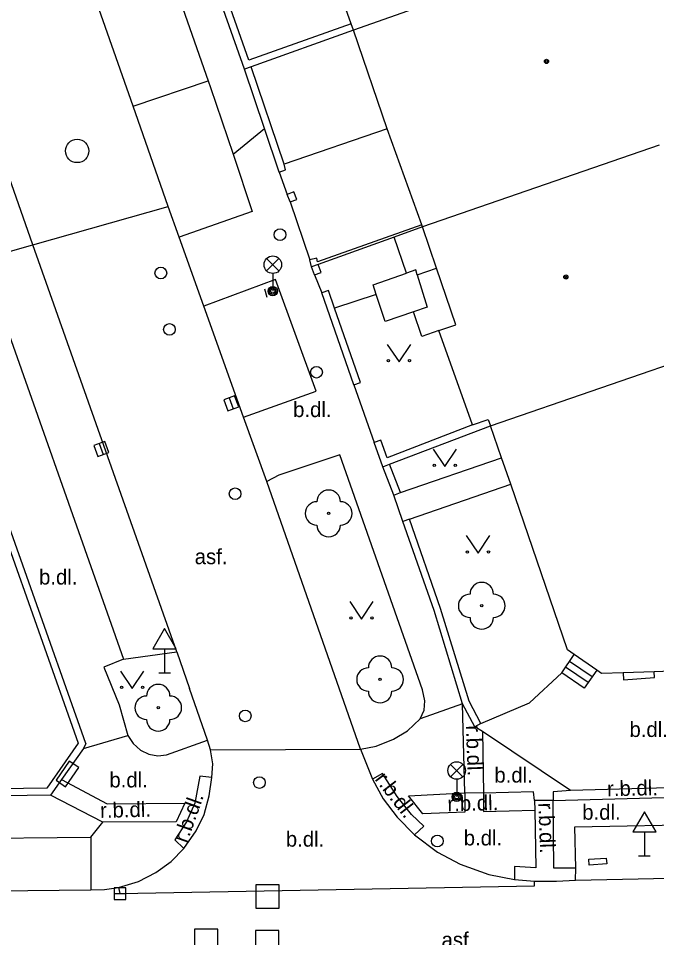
# Model space of a CAD drawing. Extents: x -596229 to -595156, y -1161237 to -1159376.
# Drawn here: x -595847.54 to -595820.24, y -1160892.51 to -1160853.2 of the extents above; entities that cross this region are included whole.
import ezdxf

# ---------------------------------------------------------------- set-up
doc = ezdxf.new("R2010")
doc.units = 0
for name, color, linetype in [('Level 22', 7, 'Continuous'), ('Level 24', 7, 'Continuous'), ('Level 26', 7, 'Continuous'), ('Level 27', 7, 'Continuous'), ('Level 28', 7, 'Continuous'), ('Level 31', 7, 'Continuous'), ('Level 33', 7, 'Continuous'), ('Level 34', 7, 'Continuous'), ('Level 36', 7, 'Continuous'), ('Level 39', 7, 'Continuous'), ('slaboproud - povrch.  znaky a tel. budka skut. velikost', 7, 'Continuous'), ('Specificka linie pasportu komunikaci', 7, 'Continuous'), ('TM - budovy zdene_ betonove - VP', 7, 'Continuous'), ('TM - chodniky - VP', 7, 'Continuous'), ('TM - komunikace - VP', 7, 'Continuous'), ('TM - letecke snimky - pomocna linie', 7, 'Continuous'), ('TM - plot drateny_ kovovy - VP', 7, 'Continuous'), ('TM - podezdivka plotu - VP', 7, 'Continuous'), ('TM - popis povrchu', 7, 'Continuous'), ('TM - rozhrani mezi zpev. plochami mezi sebou - VP', 7, 'Continuous'), ('TM - rozhrani ploch obecne - VP', 7, 'Continuous'), ('TM - schody - VP', 7, 'Continuous'), ('TM - vjezd na pozemek', 7, 'Continuous'), ('TM - zabradli - VP', 7, 'Continuous')]:
    doc.layers.add(name, color=color, linetype=linetype)

msp = doc.modelspace()

# ---------------------------------------------------------------- linework, layer by layer
at = {"layer": 'Level 22'}
for centre in [(-595834.27, -1160874.37), (-595827.72, -1160878.32), (-595832.07, -1160881.47), (-595841.56, -1160882.68)]:
    msp.add_circle(centre, 0.05, dxfattribs=at)
for centre, start, end in [((-595834.27, -1160873.87), 0, 180), ((-595834.77, -1160874.37), 90, 270), ((-595833.77, -1160874.37), 270, 90), ((-595834.27, -1160874.87), 180, 0), ((-595827.72, -1160877.82), 0, 180), ((-595828.22, -1160878.32), 90, 270), ((-595827.22, -1160878.32), 270, 90), ((-595827.72, -1160878.82), 180, 0), ((-595832.07, -1160880.97), 0, 180), ((-595832.57, -1160881.47), 90, 270), ((-595831.57, -1160881.47), 270, 90), ((-595841.56, -1160882.18), 0, 180), ((-595832.07, -1160881.97), 180, 0), ((-595842.06, -1160882.68), 90, 270), ((-595841.06, -1160882.68), 270, 90), ((-595841.56, -1160883.18), 180, 0)]:
    msp.add_arc(centre, 0.5, start, end, dxfattribs=at)
at = {"layer": 'Level 24'}
msp.add_lwpolyline([(-595845.369, -1160884.958), (-595845.934, -1160885.783), (-595845.522, -1160886.066), (-595844.957, -1160885.24)], close=True, dxfattribs=at)
at = {"layer": 'Level 26'}
for points in [[(-595837.39, -1160891.25), (-595836.39, -1160891.25), (-595836.39, -1160890.25), (-595837.39, -1160890.25)], [(-595840.01, -1160893.15), (-595839.01, -1160893.15), (-595839.01, -1160892.15), (-595840.01, -1160892.15)], [(-595837.4, -1160893.21), (-595836.4, -1160893.21), (-595836.4, -1160892.21), (-595837.4, -1160892.21)]]:
    msp.add_lwpolyline(points, close=True, dxfattribs=at)
at = {"layer": 'Level 27'}
for p, q in [((-595838.527, -1160869.425), (-595838.353, -1160869.894)), ((-595844.087, -1160871.386), (-595843.913, -1160871.854)), ((-595843.45, -1160890.63), (-595842.95, -1160890.63))]:
    msp.add_line(p, q, dxfattribs=at)
for points in [[(-595838.761, -1160869.512), (-595838.588, -1160869.981), (-595838.119, -1160869.808), (-595838.292, -1160869.339)], [(-595844.321, -1160871.472), (-595844.148, -1160871.941), (-595843.679, -1160871.768), (-595843.852, -1160871.299)], [(-595843.45, -1160890.88), (-595842.95, -1160890.88), (-595842.95, -1160890.38), (-595843.45, -1160890.38)]]:
    msp.add_lwpolyline(points, close=True, dxfattribs=at)
msp.add_circle((-595845.03, -1160858.87), 0.5, dxfattribs=at)
at = {"layer": 'Level 28'}
for centre in [(-595836.35, -1160862.45), (-595841.45, -1160864.09), (-595841.08, -1160866.5), (-595834.79, -1160868.33), (-595838.27, -1160873.53)]:
    msp.add_circle(centre, 0.25, dxfattribs=at)
at = {"layer": 'Level 31'}
for centre in [(-595837.84, -1160883.03), (-595837.23, -1160885.88), (-595829.62, -1160888.38)]:
    msp.add_circle(centre, 0.25, dxfattribs=at)
at = {"layer": 'Level 33'}
for p, q in [((-595836.925, -1160864), (-595836.395, -1160863.47)), ((-595836.925, -1160863.47), (-595836.395, -1160864)), ((-595836.66, -1160864.11), (-595836.66, -1160864.86)), ((-595829.055, -1160885.63), (-595828.525, -1160885.1)), ((-595829.055, -1160885.1), (-595828.525, -1160885.63)), ((-595828.79, -1160885.74), (-595828.79, -1160886.49))]:
    msp.add_line(p, q, dxfattribs=at)
for centre, radius in [((-595836.66, -1160863.735), 0.375), ((-595836.66, -1160864.86), 0.2), ((-595836.66, -1160864.86), 0.145), ((-595836.66, -1160864.86), 0.0876), ((-595828.79, -1160885.365), 0.375), ((-595828.79, -1160886.49), 0.2), ((-595828.79, -1160886.49), 0.145), ((-595828.79, -1160886.49), 0.0876)]:
    msp.add_circle(centre, radius, dxfattribs=at)
at = {"layer": 'Level 34'}
for p, q in [((-595841.29, -1160880.162), (-595841.29, -1160881.18)), ((-595841.54, -1160881.18), (-595841.04, -1160881.18)), ((-595820.76, -1160887.992), (-595820.76, -1160889.01)), ((-595821.01, -1160889.01), (-595820.51, -1160889.01))]:
    msp.add_line(p, q, dxfattribs=at)
for points in [[(-595841.79, -1160880.162), (-595840.79, -1160880.162), (-595841.29, -1160879.296)], [(-595821.26, -1160887.992), (-595820.26, -1160887.992), (-595820.76, -1160887.126)]]:
    msp.add_lwpolyline(points, close=True, dxfattribs=at)
at = {"layer": 'Level 36'}
for points in [[(-595831.76, -1160867.14), (-595831.26, -1160867.89), (-595830.76, -1160867.14)], [(-595829.8, -1160871.62), (-595829.3, -1160872.37), (-595828.8, -1160871.62)], [(-595828.38, -1160875.32), (-595827.88, -1160876.07), (-595827.38, -1160875.32)], [(-595833.37, -1160878.14), (-595832.87, -1160878.89), (-595832.37, -1160878.14)], [(-595843.18, -1160881.11), (-595842.68, -1160881.86), (-595842.18, -1160881.11)]]:
    msp.add_lwpolyline(points, dxfattribs=at)
for centre in [(-595831.71, -1160867.84), (-595830.811, -1160867.84), (-595829.75, -1160872.32), (-595828.851, -1160872.32), (-595828.33, -1160876.02), (-595827.431, -1160876.02), (-595833.32, -1160878.84), (-595832.421, -1160878.84), (-595843.13, -1160881.81), (-595842.231, -1160881.81)]:
    msp.add_circle(centre, 0.05, dxfattribs=at)
at = {"layer": 'Level 39'}
for centre, radius in [((-595824.95, -1160855.04), 0.09), ((-595824.95, -1160855.04), 0.0398), ((-595824.12, -1160864.26), 0.09), ((-595824.12, -1160864.26), 0.0398)]:
    msp.add_circle(centre, radius, dxfattribs=at)
at = {"layer": 'slaboproud - povrch.  znaky a tel. budka skut. velikost'}
msp.add_lwpolyline([(-595823.14, -1160889.16), (-595822.39, -1160889.11), (-595822.37, -1160889.36), (-595823.12, -1160889.41), (-595823.14, -1160889.16)], dxfattribs=at)
at = {"layer": 'Specificka linie pasportu komunikaci'}
for points in [[(-595845.03, -1160843.46), (-595843.86, -1160843.2), (-595839.42, -1160855.87)], [(-595842.64, -1160856.96), (-595844.83, -1160850.7), (-595847.01, -1160844.7)], [(-595842.64, -1160856.96), (-595839.42, -1160855.87)], [(-595839.42, -1160855.87), (-595839.32, -1160856.15), (-595838.36, -1160859)], [(-595841.13, -1160861.25), (-595842.64, -1160856.96)], [(-595838.36, -1160859), (-595837.01, -1160857.91)], [(-595838.36, -1160859), (-595837.54, -1160861.46), (-595840.67, -1160862.55)], [(-595846.92, -1160862.88), (-595841.13, -1160861.25)], [(-595840.67, -1160862.55), (-595841.13, -1160861.25)], [(-595839.61, -1160865.5), (-595840.67, -1160862.55)], [(-595849.1, -1160863.49), (-595847.02, -1160862.91), (-595846.92, -1160862.88)], [(-595837.91, -1160870.25), (-595834.81, -1160869.14), (-595836.54, -1160864.36), (-595839.61, -1160865.5)], [(-595837.91, -1160870.25), (-595839.61, -1160865.5)], [(-595836.92, -1160873), (-595837.91, -1160870.25)], [(-595831.09, -1160874.71), (-595831.48, -1160873.59)], [(-595844.45, -1160888.21), (-595843.93, -1160887.57)]]:
    msp.add_lwpolyline(points, dxfattribs=at)
at = {"layer": 'TM - budovy zdene_ betonove - VP'}
for points in [[(-595821.65, -1160849.62), (-595833.21, -1160853.71)], [(-595833.31, -1160853.43), (-595834.5, -1160850.06)], [(-595833.21, -1160853.71), (-595833.31, -1160853.43)], [(-595831.77, -1160857.93), (-595833.21, -1160853.71)], [(-595830.28, -1160862.03), (-595831.77, -1160857.93)], [(-595820.13, -1160858.62), (-595830.25, -1160862.12)], [(-595830.25, -1160862.12), (-595830.28, -1160862.03)], [(-595829.65, -1160863.88), (-595830.25, -1160862.12)], [(-595828.83, -1160866.3), (-595829.65, -1160863.88)], [(-595829.56, -1160866.55), (-595828.83, -1160866.3)], [(-595828.12, -1160870.58), (-595829.56, -1160866.55)], [(-595827.34, -1160870.63), (-595817.9, -1160867.37)], [(-595828.12, -1160870.58), (-595827.44, -1160870.35)], [(-595827.44, -1160870.35), (-595827.34, -1160870.63)], [(-595826.87, -1160871.99), (-595827.34, -1160870.63)], [(-595826.48, -1160873.12), (-595826.87, -1160871.99)], [(-595824.05, -1160880.2), (-595826.48, -1160873.12)], [(-595823.76, -1160880.4), (-595824.05, -1160880.2)], [(-595822.8, -1160881.07), (-595823.76, -1160880.4)], [(-595822.6, -1160881.21), (-595822.8, -1160881.07)], [(-595821.67, -1160881.18), (-595822.6, -1160881.21)], [(-595820.34, -1160881.14), (-595821.67, -1160881.18)], [(-595818.48, -1160881.07), (-595820.34, -1160881.14)]]:
    msp.add_lwpolyline(points, dxfattribs=at)
at = {"layer": 'TM - chodniky - VP'}
for points in [[(-595830.35, -1160883.16), (-595830.19, -1160882.79), (-595830.15, -1160882.39), (-595830.25, -1160881.91), (-595833.79, -1160871.86), (-595836.4, -1160872.73), (-595836.92, -1160873)], [(-595831.2, -1160873.48), (-595826.87, -1160871.99)], [(-595830.81, -1160874.61), (-595826.48, -1160873.12)], [(-595843.04, -1160880.6), (-595843.89, -1160880.94), (-595843.23, -1160882.55), (-595842.86, -1160883.86)], [(-595827.76, -1160883.35), (-595825.67, -1160882.47), (-595824.3, -1160881.18)], [(-595832.91, -1160884.45), (-595832.23, -1160884.32), (-595831.5, -1160884.03), (-595830.9, -1160883.66), (-595830.35, -1160883.16)], [(-595842.86, -1160883.86), (-595842.63, -1160884.21), (-595842.32, -1160884.49), (-595841.96, -1160884.66), (-595841.58, -1160884.73), (-595841.21, -1160884.7), (-595839.46, -1160884.07)], [(-595823.69, -1160889.54), (-595823.74, -1160887.77), (-595817.76, -1160887.66)], [(-595867.45, -1160888.44), (-595844.45, -1160888.21)], [(-595844.45, -1160888.21), (-595844.45, -1160890.47)], [(-595823.71, -1160890.05), (-595823.69, -1160889.54)]]:
    msp.add_lwpolyline(points, dxfattribs=at)
at = {"layer": 'TM - komunikace - VP'}
for points in [[(-595849.1, -1160863.49), (-595843.04, -1160880.6)], [(-595832.91, -1160884.45), (-595836.92, -1160873)], [(-595843.04, -1160880.6), (-595840.76, -1160880.29)], [(-595840.76, -1160880.29), (-595840.22, -1160881.85)], [(-595839.46, -1160884.07), (-595840.22, -1160881.85)], [(-595839.32, -1160884.48), (-595839.46, -1160884.07)], [(-595839.27, -1160885.66), (-595839.23, -1160885.08), (-595839.32, -1160884.48)], [(-595832.91, -1160884.45), (-595832.4, -1160885.73)], [(-595840.47, -1160888.7), (-595839.94, -1160887.95), (-595839.59, -1160887.24), (-595839.38, -1160886.44), (-595839.27, -1160885.66)], [(-595832.4, -1160885.73), (-595831.94, -1160886.57), (-595831.34, -1160887.36), (-595830.6, -1160888.11)], [(-595830.6, -1160888.11), (-595829.61, -1160888.86), (-595828.65, -1160889.37), (-595827.41, -1160889.81), (-595826.32, -1160890.02)], [(-595843.26, -1160890.36), (-595842.41, -1160890.11), (-595841.66, -1160889.72), (-595841.01, -1160889.25), (-595840.47, -1160888.7)], [(-595826.32, -1160890.02), (-595825.46, -1160890.1)], [(-595825.46, -1160890.1), (-595824.52, -1160890.09), (-595823.71, -1160890.05)], [(-595823.71, -1160890.05), (-595817.69, -1160889.93)], [(-595867.42, -1160890.71), (-595844.45, -1160890.47)], [(-595844.45, -1160890.47), (-595843.86, -1160890.45), (-595843.26, -1160890.36)]]:
    msp.add_lwpolyline(points, dxfattribs=at)
at = {"layer": 'TM - letecke snimky - pomocna linie'}
for points in [[(-595846.92, -1160862.88), (-595850.16, -1160853.68)], [(-595832.23, -1160865.01), (-595834.02, -1160865.59)]]:
    msp.add_lwpolyline(points, dxfattribs=at)
at = {"layer": 'TM - plot drateny_ kovovy - VP'}
for points in [[(-595837.69, -1160854.99), (-595839.06, -1160851.1)], [(-595833.31, -1160853.43), (-595837.69, -1160854.99)], [(-595836.18, -1160859.43), (-595837.59, -1160855.27)], [(-595836.39, -1160859.77), (-595836.11, -1160859.67), (-595836.18, -1160859.43)], [(-595835.91, -1160861.05), (-595835.63, -1160860.94), (-595835.76, -1160860.62), (-595836.04, -1160860.73)], [(-595830.28, -1160862.03), (-595834.74, -1160863.61), (-595834.78, -1160863.46), (-595835.07, -1160863.53)], [(-595834.87, -1160864.16), (-595834.59, -1160864.06), (-595834.72, -1160863.72)], [(-595834.02, -1160865.59), (-595834.28, -1160864.83), (-595834.56, -1160864.93)], [(-595833.19, -1160868.87), (-595832.91, -1160868.77), (-595834.02, -1160865.59)], [(-595849.84, -1160870.51), (-595844.98, -1160884.19)], [(-595828.12, -1160870.58), (-595831.77, -1160871.99), (-595832.04, -1160871.23), (-595832.32, -1160871.33)], [(-595831.2, -1160873.48), (-595831.67, -1160872.27)], [(-595831.48, -1160873.59), (-595831.2, -1160873.48)], [(-595830.81, -1160874.61), (-595831.09, -1160874.71)], [(-595827.76, -1160883.35), (-595828.26, -1160882.4), (-595829.48, -1160878.43), (-595830.81, -1160874.61)], [(-595844.98, -1160884.19), (-595846.33, -1160886.12), (-595867.27, -1160886.42), (-595867.27, -1160886.72)]]:
    msp.add_lwpolyline(points, dxfattribs=at)
at = {"layer": 'TM - podezdivka plotu - VP'}
for points in [[(-595837.87, -1160855.37), (-595841.21, -1160845.94)], [(-595833.21, -1160853.71), (-595837.59, -1160855.27)], [(-595837.59, -1160855.27), (-595837.87, -1160855.37)], [(-595837.01, -1160857.91), (-595837.87, -1160855.37)], [(-595836.39, -1160859.77), (-595837.01, -1160857.91)], [(-595835.91, -1160861.05), (-595836.04, -1160860.73)], [(-595830.25, -1160862.12), (-595831.47, -1160862.56)], [(-595831.47, -1160862.56), (-595834.72, -1160863.72)], [(-595835, -1160863.82), (-595835.07, -1160863.53)], [(-595834.72, -1160863.72), (-595835, -1160863.82)], [(-595834.87, -1160864.16), (-595835, -1160863.82)], [(-595833.19, -1160868.87), (-595834.56, -1160864.93)], [(-595844.66, -1160884.21), (-595849.55, -1160870.41)], [(-595831.67, -1160872.27), (-595827.34, -1160870.63)], [(-595831.95, -1160872.38), (-595832.32, -1160871.33)], [(-595831.95, -1160872.38), (-595831.67, -1160872.27)], [(-595831.48, -1160873.59), (-595831.95, -1160872.38)], [(-595828.54, -1160882.51), (-595829.76, -1160878.52), (-595831.09, -1160874.71)], [(-595828.02, -1160883.49), (-595828.54, -1160882.51)], [(-595827.76, -1160883.35), (-595828.02, -1160883.49)], [(-595844.66, -1160884.21), (-595844.76, -1160884.42)], [(-595844.76, -1160884.42), (-595845.7, -1160885.75)], [(-595845.7, -1160885.75), (-595846.17, -1160886.42)], [(-595846.17, -1160886.42), (-595867.27, -1160886.72)]]:
    msp.add_lwpolyline(points, dxfattribs=at)
at = {"layer": 'TM - rozhrani mezi zpev. plochami mezi sebou - VP'}
for points in [[(-595840.76, -1160880.29), (-595846.92, -1160862.88)], [(-595828.54, -1160882.51), (-595830.35, -1160883.16)], [(-595828.44, -1160886.32), (-595828.54, -1160882.51)], [(-595844.76, -1160884.42), (-595842.86, -1160883.86)], [(-595827.69, -1160883.7), (-595827.65, -1160886.33)], [(-595823.92, -1160886.22), (-595827.69, -1160883.7)], [(-595839.32, -1160884.48), (-595832.91, -1160884.45)], [(-595830.6, -1160888.11), (-595830.2, -1160887.75), (-595830.73, -1160887.24), (-595831.34, -1160886.47), (-595831.96, -1160885.49), (-595832.4, -1160885.73)], [(-595845.7, -1160885.75), (-595843.75, -1160886.79), (-595840.43, -1160886.76), (-595840.79, -1160887.56), (-595843.93, -1160887.57)], [(-595839.27, -1160885.66), (-595839.78, -1160885.6), (-595839.99, -1160886.76), (-595840.35, -1160887.56), (-595840.85, -1160888.33), (-595840.47, -1160888.7)], [(-595825.46, -1160886.64), (-595825.51, -1160886.28), (-595827.65, -1160886.33)], [(-595823.92, -1160886.22), (-595824.66, -1160886.27), (-595824.67, -1160886.65)], [(-595813.94, -1160885.95), (-595823.92, -1160886.22)], [(-595843.93, -1160887.57), (-595846.17, -1160886.42)], [(-595828.44, -1160887.14), (-595830.24, -1160887.22), (-595830.85, -1160886.44), (-595828.44, -1160886.32)], [(-595827.65, -1160886.33), (-595828.44, -1160886.32)], [(-595828.44, -1160886.32), (-595828.44, -1160887.14)], [(-595827.65, -1160886.33), (-595827.64, -1160887.11), (-595825.45, -1160887.06)], [(-595825.46, -1160886.64), (-595825.45, -1160887.06)], [(-595824.67, -1160886.65), (-595825.46, -1160886.64)], [(-595824.67, -1160886.65), (-595817.8, -1160886.46)], [(-595823.69, -1160889.54), (-595824.63, -1160889.54), (-595824.67, -1160886.65)], [(-595825.45, -1160887.06), (-595825.41, -1160889.52), (-595826.32, -1160889.47), (-595826.32, -1160890.02)], [(-595843.26, -1160890.36), (-595843.2, -1160890.63), (-595825.47, -1160890.3), (-595825.46, -1160890.1)]]:
    msp.add_lwpolyline(points, dxfattribs=at)
at = {"layer": 'TM - rozhrani ploch obecne - VP'}
for points in [[(-595831.77, -1160857.93), (-595836.18, -1160859.43)], [(-595830.94, -1160864.09), (-595831.47, -1160862.56)], [(-595830.48, -1160864.16), (-595829.65, -1160863.88)], [(-595832.23, -1160865.01), (-595832.36, -1160864.59), (-595830.94, -1160864.09)], [(-595830.48, -1160864.16), (-595830.54, -1160863.95), (-595830.94, -1160864.09)], [(-595830.48, -1160864.16), (-595830.05, -1160865.55), (-595830.64, -1160865.75)], [(-595830.64, -1160865.75), (-595831.85, -1160866.16), (-595832.23, -1160865.01)], [(-595829.56, -1160866.55), (-595830.29, -1160866.8), (-595830.64, -1160865.75)], [(-595824.3, -1160881.18), (-595823.76, -1160880.4)], [(-595822.8, -1160881.07), (-595823.34, -1160881.84), (-595824.3, -1160881.18)], [(-595821.67, -1160881.18), (-595821.66, -1160881.49), (-595820.33, -1160881.39), (-595820.34, -1160881.14)], [(-595827.69, -1160883.7), (-595828.02, -1160883.49)]]:
    msp.add_lwpolyline(points, dxfattribs=at)
at = {"layer": 'TM - schody - VP'}
for points in [[(-595823.96, -1160880.69), (-595823, -1160881.35)], [(-595824.13, -1160880.93), (-595823.17, -1160881.59)]]:
    msp.add_lwpolyline(points, dxfattribs=at)
at = {"layer": 'TM - vjezd na pozemek'}
for points in [[(-595836.39, -1160859.77), (-595836.04, -1160860.73)], [(-595835.91, -1160861.05), (-595835.07, -1160863.53)], [(-595834.87, -1160864.16), (-595834.56, -1160864.93)], [(-595833.19, -1160868.87), (-595832.32, -1160871.33)]]:
    msp.add_lwpolyline(points, dxfattribs=at)
at = {"layer": 'TM - zabradli - VP'}
msp.add_lwpolyline([(-595837.02, -1160864.77), (-595836.91, -1160865.12)], dxfattribs=at)

# ---------------------------------------------------------------- texts
at = {"layer": 'TM - popis povrchu'}
for s, p in [('b.dl.', (-595835.79, -1160870.25)), ('asf.', (-595840, -1160876.54)), ('b.dl.', (-595846.66, -1160877.41)), ('b.dl.', (-595821.4, -1160883.93)), ('b.dl.', (-595843.65, -1160886.09)), ('b.dl.', (-595827.18, -1160885.88)), ('b.dl.', (-595823.42, -1160887.47)), ('b.dl.', (-595836.1, -1160888.62)), ('b.dl.', (-595828.49, -1160888.57)), ('asf.', (-595829.44, -1160892.93))]:
    msp.add_text(s, height=0.65, dxfattribs=at).set_placement(p)
for rotation, p in [(272.09, (-595828.4, -1160883.44)), (307.66, (-595832.32, -1160885.74)), (1.39, (-595822.35, -1160886.47)), (1.39, (-595844.04, -1160887.39)), (70.4, (-595840.33, -1160888.5)), (1.39, (-595829.18, -1160887.11)), (272.09, (-595825.3, -1160886.75))]:
    msp.add_text('r.b.dl.', height=0.65, rotation=rotation, dxfattribs=at).set_placement(p)

doc.saveas('drawing.dxf')
